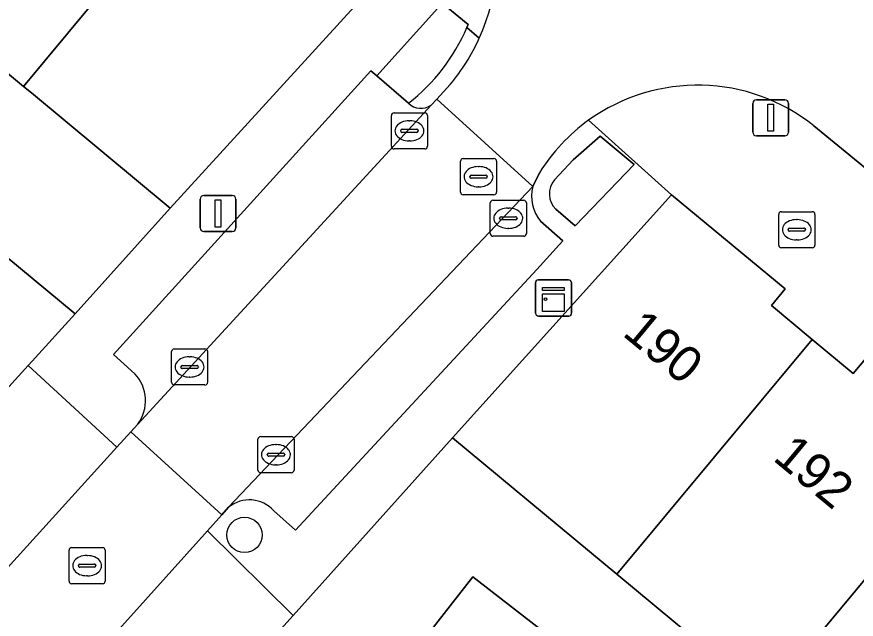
# Model space of a CAD drawing. Extents: x 161881 to 162523, y 381678 to 382381.
# Drawn here: x 162365 to 162388.24, y 381913.58 to 381930.28 of the extents above; entities that cross this region are included whole.
import ezdxf

# ---------------------------------------------------------------- set-up
doc = ezdxf.new("R2010")
doc.units = 0
for name, color, linetype in [('IMGEO_Boom', 7, 'Continuous'), ('IMGEO_Brandkraan', 7, 'Continuous'), ('IMGEO_Erf', 7, 'Continuous'), ('IMGEO_Groenvoorziening', 7, 'Continuous'), ('IMGEO_Kast', 7, 'Continuous'), ('IMGEO_Kolk', 7, 'Continuous'), ('IMGEO_Lichtmast', 7, 'Continuous'), ('IMGEO_Muur', 7, 'Continuous'), ('IMGEO_Pand', 7, 'Continuous'), ('IMGEO_Pand_nummerreeks', 7, 'Continuous'), ('IMGEO_Parkeervlak_open', 7, 'Continuous'), ('IMGEO_Rijbaan_lokaal_open', 7, 'Continuous'), ('IMGEO_Rioolput', 7, 'Continuous'), ('IMGEO_Voetpad_open', 7, 'Continuous')]:
    doc.layers.add(name, color=color, linetype=linetype)

msp = doc.modelspace()

# ---------------------------------------------------------------- linework, layer by layer
at = {"layer": 'IMGEO_Boom'}
msp.add_circle((162371.304, 381915.913), 0.489, dxfattribs=at)
at = {"layer": 'IMGEO_Brandkraan'}
for p, q in [((162386.098, 381923.947), (162386.098, 381924.799)), ((162386.173, 381924.873), (162387.025, 381924.873)), ((162387.099, 381924.799), (162387.099, 381923.947)), ((162386.586, 381924.653), (162386.611, 381924.653)), ((162386.357, 381924.367), (162386.357, 381924.379)), ((162386.795, 381924.33), (162386.397, 381924.33)), ((162386.4, 381924.416), (162386.798, 381924.416)), ((162386.841, 381924.379), (162386.841, 381924.367)), ((162386.609, 381924.093), (162386.584, 381924.093)), ((162387.025, 381923.873), (162386.173, 381923.873))]:
    msp.add_line(p, q, dxfattribs=at)
for points in [[(162386.098, 381923.947), (162386.098, 381924.799)], [(162386.173, 381924.873), (162387.025, 381924.873)], [(162387.099, 381924.799), (162387.099, 381923.947)], [(162387.025, 381923.873), (162386.173, 381923.873)]]:
    msp.add_lwpolyline(points, dxfattribs=at)
for centre, radius, start, end in [((162386.175, 381924.797), 0.0765, 91.552, 178.448), ((162386.175, 381924.797), 0.0765, 91.552, 178.448), ((162387.023, 381924.797), 0.0765, 1.552, 88.448), ((162387.023, 381924.797), 0.0765, 1.552, 88.448), ((162386.397, 381924.376), 0.0403, 85.8775, 175.7526), ((162386.394, 381924.366), 0.0366, 178.938, 274.7102), ((162386.798, 381924.373), 0.043, 264.8664, 352.4533), ((162386.802, 381924.378), 0.0386, 1.7309, 96.639), ((162386.175, 381923.949), 0.0765, 181.552, 268.448), ((162386.175, 381923.949), 0.0765, 181.552, 268.448), ((162387.023, 381923.949), 0.0765, 271.552, 358.448), ((162387.023, 381923.949), 0.0765, 271.552, 358.448)]:
    msp.add_arc(centre, radius, start, end, dxfattribs=at)
for centre, major_axis, ratio, start_param, end_param in [((162386.585, 381924.373), (-0.387, 0.002), 0.722429, 4.712389, 7.853982), ((162386.61, 381924.373), (-0.39, 0.002), 0.717154, 1.570796, 4.712389)]:
    msp.add_ellipse(centre, major_axis=major_axis, ratio=ratio, start_param=start_param, end_param=end_param, dxfattribs=at)
at = {"layer": 'IMGEO_Erf'}
for points in [[(162362.768, 381925.233), (162366.613, 381922.037), (162369.246, 381924.97), (162365.401, 381928.166), (162365.186, 381928.345), (162361.108, 381931.735)], [(162383.306, 381891.633), (162388.53, 381897.921), (162390.835, 381896.006), (162396.322, 381902.611), (162394.016, 381904.526), (162392.495, 381902.696), (162388.778, 381905.783), (162388.37, 381906.122), (162389.891, 381907.952), (162385.752, 381911.39), (162381.619, 381914.822), (162380.911, 381915.41), (162377.065, 381918.605), (162372.654, 381913.683), (162372.054, 381913.013), (162369.869, 381910.575), (162373.57, 381907.213), (162375.958, 381905.043), (162371.892, 381900.569), (162371.822, 381900.491), (162373.921, 381898.584), (162369.929, 381894.191), (162365.442, 381898.267), (162361.741, 381901.629)]]:
    msp.add_lwpolyline(points, dxfattribs=at)
msp.add_lwpolyline([(162376.064, 381908.136), (162374.161, 381909.62), (162373.826, 381909.882), (162377.626, 381914.754), (162380.015, 381912.891), (162377.671, 381910.07), (162381.786, 381906.65), (162380.179, 381904.716)], close=True, dxfattribs=at)
at = {"layer": 'IMGEO_Groenvoorziening'}
for points in [[(162377.462, 381929.977), (162377.495, 381930.057), (162376.782, 381930.65), (162376.741, 381930.606), (162374.965, 381928.638), (162375.845, 381927.879)], [(162379.923, 381924.94), (162380.462, 381924.484), (162382.096, 381926.178), (162381.155, 381926.963), (162380.405, 381926.31), (162379.887, 381925.758)]]:
    msp.add_lwpolyline(points, dxfattribs=at)
for centre, radius, start, end in [((162372.55, 381932.091), 5.347, 308.0367, 336.718), ((162380.361, 381925.369), 0.613, 140.6598, 224.3801)]:
    msp.add_arc(centre, radius, start, end, dxfattribs=at)
at = {"layer": 'IMGEO_Kast'}
for p, q in [((162379.36, 381922.056), (162379.36, 381922.897)), ((162379.36, 381922.897), (162379.36, 381922.056)), ((162379.435, 381922.981), (162380.276, 381922.981)), ((162380.276, 381922.981), (162379.435, 381922.981)), ((162380.36, 381922.906), (162380.36, 381922.065)), ((162380.36, 381922.065), (162380.36, 381922.906)), ((162380.285, 381921.981), (162379.444, 381921.981)), ((162379.444, 381921.981), (162380.285, 381921.981))]:
    msp.add_line(p, q, dxfattribs=at)
for points in [[(162379.555, 381922.771), (162380.155, 381922.771), (162380.155, 381922.686), (162379.555, 381922.686), (162379.555, 381922.771)], [(162379.555, 381922.596), (162380.155, 381922.596), (162380.155, 381922.107), (162379.555, 381922.107), (162379.555, 381922.596)]]:
    msp.add_lwpolyline(points, dxfattribs=at)
msp.add_circle((162379.639, 381922.445), 0.0377, dxfattribs=at)
for centre, start, end in [((162379.438, 381922.903), 92.4484, 184.2845), ((162379.438, 381922.903), 92.4484, 184.2845), ((162380.282, 381922.903), 2.4484, 94.2845), ((162380.282, 381922.903), 2.4484, 94.2845), ((162379.438, 381922.059), 182.4484, 274.2845), ((162379.438, 381922.059), 182.4484, 274.2845), ((162380.282, 381922.059), 272.4484, 4.2845), ((162380.282, 381922.059), 272.4484, 4.2845)]:
    msp.add_arc(centre, 0.0779, start, end, dxfattribs=at)
at = {"layer": 'IMGEO_Kolk'}
for p, q in [((162375.37, 381926.687), (162375.37, 381927.539)), ((162375.445, 381927.613), (162376.297, 381927.613)), ((162376.371, 381927.539), (162376.371, 381926.687)), ((162375.858, 381927.393), (162375.883, 381927.393)), ((162375.629, 381927.107), (162375.629, 381927.119)), ((162376.067, 381927.07), (162375.669, 381927.07)), ((162375.672, 381927.156), (162376.07, 381927.156)), ((162376.113, 381927.119), (162376.113, 381927.107)), ((162375.881, 381926.833), (162375.856, 381926.833)), ((162376.297, 381926.613), (162375.445, 381926.613)), ((162378.183, 381925.191), (162379.035, 381925.191)), ((162378.108, 381924.265), (162378.108, 381925.117)), ((162378.596, 381924.971), (162378.621, 381924.971)), ((162379.109, 381925.117), (162379.109, 381924.265)), ((162378.367, 381924.685), (162378.367, 381924.697)), ((162378.41, 381924.734), (162378.808, 381924.734)), ((162378.851, 381924.697), (162378.851, 381924.685)), ((162378.805, 381924.648), (162378.407, 381924.648)), ((162378.619, 381924.411), (162378.594, 381924.411)), ((162379.035, 381924.191), (162378.183, 381924.191)), ((162369.282, 381920.143), (162369.282, 381920.995)), ((162369.357, 381921.069), (162370.209, 381921.069)), ((162370.283, 381920.995), (162370.283, 381920.143)), ((162369.77, 381920.849), (162369.795, 381920.849)), ((162369.541, 381920.563), (162369.541, 381920.575)), ((162369.979, 381920.526), (162369.581, 381920.526)), ((162369.584, 381920.612), (162369.982, 381920.612)), ((162370.025, 381920.575), (162370.025, 381920.563)), ((162369.793, 381920.289), (162369.768, 381920.289)), ((162370.209, 381920.069), (162369.357, 381920.069)), ((162371.674, 381917.711), (162371.674, 381918.563)), ((162371.749, 381918.637), (162372.601, 381918.637)), ((162372.162, 381918.417), (162372.187, 381918.417)), ((162372.675, 381918.563), (162372.675, 381917.711)), ((162371.976, 381918.18), (162372.374, 381918.18)), ((162371.933, 381918.131), (162371.933, 381918.143)), ((162372.371, 381918.094), (162371.973, 381918.094)), ((162372.417, 381918.143), (162372.417, 381918.131)), ((162372.185, 381917.857), (162372.16, 381917.857)), ((162372.601, 381917.637), (162371.749, 381917.637)), ((162366.445, 381914.635), (162366.445, 381915.487)), ((162366.52, 381915.561), (162367.372, 381915.561)), ((162367.446, 381915.487), (162367.446, 381914.635)), ((162366.933, 381915.341), (162366.958, 381915.341)), ((162366.704, 381915.055), (162366.704, 381915.067)), ((162367.142, 381915.018), (162366.744, 381915.018)), ((162366.747, 381915.104), (162367.145, 381915.104)), ((162367.188, 381915.067), (162367.188, 381915.055)), ((162366.956, 381914.781), (162366.931, 381914.781)), ((162367.372, 381914.561), (162366.52, 381914.561))]:
    msp.add_line(p, q, dxfattribs=at)
for points in [[(162375.37, 381926.687), (162375.37, 381927.539)], [(162375.445, 381927.613), (162376.297, 381927.613)], [(162376.371, 381927.539), (162376.371, 381926.687)], [(162376.297, 381926.613), (162375.445, 381926.613)], [(162378.183, 381925.191), (162379.035, 381925.191)], [(162378.108, 381924.265), (162378.108, 381925.117)], [(162379.109, 381925.117), (162379.109, 381924.265)], [(162379.035, 381924.191), (162378.183, 381924.191)], [(162369.282, 381920.143), (162369.282, 381920.995)], [(162369.357, 381921.069), (162370.209, 381921.069)], [(162370.283, 381920.995), (162370.283, 381920.143)], [(162370.209, 381920.069), (162369.357, 381920.069)], [(162371.674, 381917.711), (162371.674, 381918.563)], [(162371.749, 381918.637), (162372.601, 381918.637)], [(162372.675, 381918.563), (162372.675, 381917.711)], [(162372.601, 381917.637), (162371.749, 381917.637)], [(162366.445, 381914.635), (162366.445, 381915.487)], [(162366.52, 381915.561), (162367.372, 381915.561)], [(162367.446, 381915.487), (162367.446, 381914.635)], [(162367.372, 381914.561), (162366.52, 381914.561)]]:
    msp.add_lwpolyline(points, dxfattribs=at)
for centre, radius, start, end in [((162375.447, 381927.537), 0.0765, 91.552, 178.448), ((162375.447, 381927.537), 0.0765, 91.552, 178.448), ((162376.295, 381927.537), 0.0765, 1.552, 88.448), ((162376.295, 381927.537), 0.0765, 1.552, 88.448), ((162375.669, 381927.116), 0.0403, 85.8775, 175.7526), ((162375.666, 381927.106), 0.0366, 178.938, 274.7102), ((162376.07, 381927.113), 0.043, 264.8664, 352.4533), ((162376.074, 381927.118), 0.0386, 1.7309, 96.639), ((162375.447, 381926.689), 0.0765, 181.552, 268.448), ((162375.447, 381926.689), 0.0765, 181.552, 268.448), ((162376.295, 381926.689), 0.0765, 271.552, 358.448), ((162376.295, 381926.689), 0.0765, 271.552, 358.448), ((162378.185, 381925.115), 0.0765, 91.552, 178.448), ((162378.185, 381925.115), 0.0765, 91.552, 178.448), ((162379.033, 381925.115), 0.0765, 1.552, 88.448), ((162379.033, 381925.115), 0.0765, 1.552, 88.448), ((162378.407, 381924.694), 0.0403, 85.8775, 175.7526), ((162378.404, 381924.684), 0.0366, 178.938, 274.7102), ((162378.808, 381924.691), 0.043, 264.8664, 352.4533), ((162378.812, 381924.696), 0.0386, 1.7309, 96.639), ((162378.185, 381924.267), 0.0765, 181.552, 268.448), ((162378.185, 381924.267), 0.0765, 181.552, 268.448), ((162379.033, 381924.267), 0.0765, 271.552, 358.448), ((162379.033, 381924.267), 0.0765, 271.552, 358.448), ((162369.359, 381920.993), 0.0765, 91.552, 178.448), ((162369.359, 381920.993), 0.0765, 91.552, 178.448), ((162370.207, 381920.993), 0.0765, 1.552, 88.448), ((162370.207, 381920.993), 0.0765, 1.552, 88.448), ((162369.581, 381920.572), 0.0403, 85.8775, 175.7526), ((162369.578, 381920.562), 0.0366, 178.938, 274.7102), ((162369.982, 381920.569), 0.043, 264.8664, 352.4533), ((162369.986, 381920.574), 0.0386, 1.7309, 96.639), ((162369.359, 381920.145), 0.0765, 181.552, 268.448), ((162369.359, 381920.145), 0.0765, 181.552, 268.448), ((162370.207, 381920.145), 0.0765, 271.552, 358.448), ((162370.207, 381920.145), 0.0765, 271.552, 358.448), ((162371.751, 381918.561), 0.0765, 91.552, 178.448), ((162371.751, 381918.561), 0.0765, 91.552, 178.448), ((162372.599, 381918.561), 0.0765, 1.552, 88.448), ((162372.599, 381918.561), 0.0765, 1.552, 88.448), ((162371.973, 381918.14), 0.0403, 85.8775, 175.7526), ((162372.378, 381918.142), 0.0386, 1.7309, 96.639), ((162371.97, 381918.13), 0.0366, 178.938, 274.7102), ((162372.374, 381918.137), 0.043, 264.8664, 352.4533), ((162371.751, 381917.713), 0.0765, 181.552, 268.448), ((162371.751, 381917.713), 0.0765, 181.552, 268.448), ((162372.599, 381917.713), 0.0765, 271.552, 358.448), ((162372.599, 381917.713), 0.0765, 271.552, 358.448), ((162366.522, 381915.485), 0.0765, 91.552, 178.448), ((162366.522, 381915.485), 0.0765, 91.552, 178.448), ((162367.37, 381915.485), 0.0765, 1.552, 88.448), ((162367.37, 381915.485), 0.0765, 1.552, 88.448), ((162366.744, 381915.064), 0.0403, 85.8775, 175.7526), ((162366.741, 381915.054), 0.0366, 178.938, 274.7102), ((162367.145, 381915.061), 0.043, 264.8664, 352.4533), ((162367.149, 381915.066), 0.0386, 1.7309, 96.639), ((162366.522, 381914.637), 0.0765, 181.552, 268.448), ((162366.522, 381914.637), 0.0765, 181.552, 268.448), ((162367.37, 381914.637), 0.0765, 271.552, 358.448), ((162367.37, 381914.637), 0.0765, 271.552, 358.448)]:
    msp.add_arc(centre, radius, start, end, dxfattribs=at)
for centre, major_axis, ratio, start_param, end_param in [((162375.857, 381927.113), (-0.387, 0.002), 0.722429, 4.712389, 7.853982), ((162375.882, 381927.113), (-0.39, 0.002), 0.717154, 1.570796, 4.712389), ((162378.595, 381924.691), (-0.387, 0.002), 0.722429, 4.712389, 7.853982), ((162378.62, 381924.691), (-0.39, 0.002), 0.717154, 1.570796, 4.712389), ((162369.769, 381920.569), (-0.387, 0.002), 0.722429, 4.712389, 7.853982), ((162369.794, 381920.569), (-0.39, 0.002), 0.717154, 1.570796, 4.712389), ((162372.161, 381918.137), (-0.387, 0.002), 0.722429, 4.712389, 7.853982), ((162372.186, 381918.137), (-0.39, 0.002), 0.717154, 1.570796, 4.712389), ((162366.932, 381915.061), (-0.387, 0.002), 0.722429, 4.712389, 7.853982), ((162366.957, 381915.061), (-0.39, 0.002), 0.717154, 1.570796, 4.712389)]:
    msp.add_ellipse(centre, major_axis=major_axis, ratio=ratio, start_param=start_param, end_param=end_param, dxfattribs=at)
at = {"layer": 'IMGEO_Lichtmast'}
for p, q in [((162385.479, 381927.976), (162386.269, 381927.976)), ((162386.269, 381927.976), (162385.479, 381927.976)), ((162385.379, 381927.076), (162385.379, 381927.876)), ((162385.379, 381927.876), (162385.379, 381927.076)), ((162386.369, 381927.876), (162386.369, 381927.076)), ((162386.369, 381927.076), (162386.369, 381927.876)), ((162386.269, 381926.976), (162385.479, 381926.976)), ((162385.479, 381926.976), (162386.269, 381926.976)), ((162370.075, 381924.422), (162370.075, 381925.222)), ((162370.075, 381925.222), (162370.075, 381924.422)), ((162370.175, 381925.322), (162370.965, 381925.322)), ((162370.965, 381925.322), (162370.175, 381925.322)), ((162371.065, 381925.222), (162371.065, 381924.422)), ((162371.065, 381924.422), (162371.065, 381925.222)), ((162370.965, 381924.322), (162370.175, 381924.322)), ((162370.175, 381924.322), (162370.965, 381924.322))]:
    msp.add_line(p, q, dxfattribs=at)
for points in [[(162385.799, 381927.851), (162385.949, 381927.851), (162385.949, 381927.101), (162385.799, 381927.101), (162385.799, 381927.851)], [(162370.495, 381925.197), (162370.645, 381925.197), (162370.645, 381924.447), (162370.495, 381924.447), (162370.495, 381925.197)]]:
    msp.add_lwpolyline(points, dxfattribs=at)
for centre, start, end in [((162385.479, 381927.876), 90, 180), ((162385.479, 381927.876), 90, 180), ((162386.269, 381927.876), 0, 90), ((162386.269, 381927.876), 360, 90), ((162385.479, 381927.076), 180, 270), ((162385.479, 381927.076), 180, 270), ((162386.269, 381927.076), 270, 0), ((162386.269, 381927.076), 270, 0), ((162370.175, 381925.222), 90, 180), ((162370.175, 381925.222), 90, 180), ((162370.965, 381925.222), 0, 90), ((162370.965, 381925.222), 360, 90), ((162370.175, 381924.422), 180, 270), ((162370.175, 381924.422), 180, 270), ((162370.965, 381924.422), 270, 0), ((162370.965, 381924.422), 270, 0)]:
    msp.add_arc(centre, 0.1, start, end, dxfattribs=at)
at = {"layer": 'IMGEO_Muur'}
for points in [[(162369.246, 381924.97), (162366.613, 381922.037)], [(162377.065, 381918.605), (162372.654, 381913.683)], [(162372.654, 381913.683), (162372.054, 381913.013)]]:
    msp.add_lwpolyline(points, dxfattribs=at)
at = {"layer": 'IMGEO_Pand'}
for points in [[(162370.688, 381934.975), (162369.409, 381936.038), (162369.763, 381936.465), (162366.966, 381938.791), (162361.108, 381931.735), (162365.186, 381928.345)], [(162375.427, 381931.75), (162371.039, 381935.397), (162370.688, 381934.975), (162365.186, 381928.345), (162365.401, 381928.166), (162369.246, 381924.97)], [(162362.768, 381925.233), (162362.67, 381925.315), (162361.323, 381923.692), (162359.313, 381921.271), (162363.07, 381918.146), (162365.317, 381920.614), (162365.423, 381920.73), (162366.613, 381922.037)], [(162381.619, 381914.822), (162387.028, 381921.332), (162385.894, 381922.274), (162386.275, 381922.731), (162383.131, 381925.342), (162377.065, 381918.605), (162380.911, 381915.41)], [(162385.752, 381911.39), (162391.545, 381918.362), (162388.545, 381920.853), (162388.161, 381920.391), (162387.028, 381921.332), (162381.619, 381914.822)], [(162385.752, 381911.39), (162389.891, 381907.952), (162395.307, 381914.468), (162394.169, 381915.414), (162394.547, 381915.869), (162391.545, 381918.362)], [(162380.015, 381912.891), (162377.626, 381914.754), (162373.826, 381909.882), (162374.161, 381909.62), (162376.064, 381908.136), (162377.671, 381910.07)]]:
    msp.add_lwpolyline(points, close=True, dxfattribs=at)
at = {"layer": 'IMGEO_Parkeervlak_open'}
for points in [[(162375.845, 381927.879), (162374.965, 381928.638), (162374.804, 381928.776), (162367.672, 381920.918), (162368.264, 381920.381)], [(162368.347, 381918.986), (162376.471, 381927.827)], [(162379.286, 381925.567), (162370.863, 381916.679)], [(162372.118, 381916.58), (162372.714, 381916.046), (162379.399, 381923.266), (162380.121, 381924.063), (162379.503, 381924.613)]]:
    msp.add_lwpolyline(points, dxfattribs=at)
for centre, radius, start, end in [((162376.19, 381928.239), 0.499, 226.2051, 304.2979), ((162380.331, 381925.303), 1.078, 165.8208, 219.8085), ((162367.485, 381919.635), 1.078, 323.0217, 43.7882), ((162371.439, 381915.976), 0.909, 41.656, 129.3232)]:
    msp.add_arc(centre, radius, start, end, dxfattribs=at)
at = {"layer": 'IMGEO_Rijbaan_lokaal_open'}
for points in [[(162377.001, 381928.403), (162376.626, 381927.996), (162379.286, 381925.567), (162379.472, 381925.953)], [(162387.072, 381927.252), (162390.287, 381924.609), (162391.437, 381925.971), (162392.314, 381927.01), (162392.987, 381927.807), (162393.04, 381927.87)]]:
    msp.add_lwpolyline(points, dxfattribs=at)
for points in [[(162368.347, 381918.986), (162368.155, 381918.773), (162370.672, 381916.467), (162370.863, 381916.679), (162379.286, 381925.567), (162376.626, 381927.996), (162376.471, 381927.827)], [(162370.672, 381916.467), (162368.155, 381918.773), (162367.769, 381918.348), (162363.656, 381913.817), (162363.341, 381913.47), (162365.896, 381911.151), (162366.189, 381911.476), (162370.278, 381916.028)]]:
    msp.add_lwpolyline(points, close=True, dxfattribs=at)
for centre, radius, start, end in [((162372.822, 381931.927), 5.466, 335.7145, 57.383), ((162372.851, 381931.905), 5.43, 319.838, 335.7968), ((162383.85, 381923.218), 5.162, 51.3827, 125.7902), ((162383.871, 381923.2), 5.19, 125.8635, 147.9657)]:
    msp.add_arc(centre, radius, start, end, dxfattribs=at)
at = {"layer": 'IMGEO_Rioolput'}
for p, q in [((162377.36, 381926.343), (162378.212, 381926.343)), ((162377.285, 381925.417), (162377.285, 381926.269)), ((162377.773, 381926.123), (162377.798, 381926.123)), ((162378.286, 381926.269), (162378.286, 381925.417)), ((162377.544, 381925.837), (162377.544, 381925.849)), ((162377.587, 381925.886), (162377.985, 381925.886)), ((162378.028, 381925.849), (162378.028, 381925.837)), ((162377.982, 381925.8), (162377.584, 381925.8)), ((162377.796, 381925.563), (162377.771, 381925.563)), ((162378.212, 381925.343), (162377.36, 381925.343))]:
    msp.add_line(p, q, dxfattribs=at)
for points in [[(162377.36, 381926.343), (162378.212, 381926.343)], [(162377.285, 381925.417), (162377.285, 381926.269)], [(162378.286, 381926.269), (162378.286, 381925.417)], [(162378.212, 381925.343), (162377.36, 381925.343)]]:
    msp.add_lwpolyline(points, dxfattribs=at)
for centre, radius, start, end in [((162377.362, 381926.267), 0.0765, 91.552, 178.448), ((162377.362, 381926.267), 0.0765, 91.552, 178.448), ((162378.21, 381926.267), 0.0765, 1.552, 88.448), ((162378.21, 381926.267), 0.0765, 1.552, 88.448), ((162377.584, 381925.846), 0.0403, 85.8775, 175.7526), ((162377.989, 381925.848), 0.0386, 1.7309, 96.639), ((162377.581, 381925.836), 0.0366, 178.938, 274.7102), ((162377.985, 381925.843), 0.043, 264.8664, 352.4533), ((162377.362, 381925.419), 0.0765, 181.552, 268.448), ((162377.362, 381925.419), 0.0765, 181.552, 268.448), ((162378.21, 381925.419), 0.0765, 271.552, 358.448), ((162378.21, 381925.419), 0.0765, 271.552, 358.448)]:
    msp.add_arc(centre, radius, start, end, dxfattribs=at)
for centre, major_axis, ratio, start_param, end_param in [((162377.772, 381925.843), (-0.387, 0.002), 0.722429, 4.712389, 7.853982), ((162377.797, 381925.843), (-0.39, 0.002), 0.717154, 1.570796, 4.712389)]:
    msp.add_ellipse(centre, major_axis=major_axis, ratio=ratio, start_param=start_param, end_param=end_param, dxfattribs=at)
at = {"layer": 'IMGEO_Voetpad_open'}
for points in [[(162363.876, 381941.359), (162366.966, 381938.791), (162369.763, 381936.465), (162369.409, 381936.038), (162370.688, 381934.975), (162371.039, 381935.397), (162375.427, 381931.75), (162376.741, 381930.606), (162376.782, 381930.65), (162377.495, 381930.057), (162377.462, 381929.977), (162377.804, 381929.679)], [(162374.804, 381928.776), (162374.965, 381928.638), (162376.741, 381930.606), (162375.427, 381931.75), (162369.246, 381924.97), (162366.613, 381922.037), (162365.423, 381920.73), (162365.317, 381920.614), (162367.769, 381918.348), (162368.155, 381918.773), (162368.347, 381918.986)], [(162377.804, 381929.679), (162377.462, 381929.977)], [(162368.264, 381920.381), (162367.672, 381920.918), (162374.804, 381928.776)], [(162376.471, 381927.827), (162376.626, 381927.996), (162377.001, 381928.403)], [(162383.131, 381925.342), (162380.831, 381927.406)], [(162380.831, 381927.406), (162383.131, 381925.342), (162386.275, 381922.731), (162385.894, 381922.274), (162387.028, 381921.332), (162388.161, 381920.391), (162388.545, 381920.853), (162391.545, 381918.362), (162394.547, 381915.869), (162394.169, 381915.414), (162395.307, 381914.468), (162396.443, 381913.525), (162396.791, 381913.944), (162399.779, 381911.463), (162402.766, 381908.982), (162402.423, 381908.569), (162403.544, 381907.638), (162404.664, 381906.707), (162405.036, 381907.154), (162408.147, 381904.571), (162416.178, 381897.901), (162417.532, 381897.014)], [(162392.553, 381922.745), (162390.287, 381924.609), (162387.072, 381927.252)], [(162379.887, 381925.758), (162380.405, 381926.31), (162381.155, 381926.963), (162382.096, 381926.178), (162380.462, 381924.484), (162379.923, 381924.94)], [(162379.472, 381925.953), (162379.286, 381925.567)], [(162370.863, 381916.679), (162370.672, 381916.467), (162370.278, 381916.028), (162372.654, 381913.683), (162377.065, 381918.605), (162383.131, 381925.342)], [(162379.503, 381924.613), (162380.121, 381924.063), (162379.399, 381923.266), (162372.714, 381916.046), (162372.118, 381916.58)]]:
    msp.add_lwpolyline(points, dxfattribs=at)
for points in [[(162363.656, 381913.817), (162367.769, 381918.348), (162365.317, 381920.614), (162363.07, 381918.146), (162362.239, 381917.205), (162361.239, 381916.098)], [(162372.054, 381913.013), (162372.654, 381913.683), (162370.278, 381916.028), (162366.189, 381911.476), (162367.357, 381910.439), (162368.679, 381909.266), (162369.869, 381910.575)]]:
    msp.add_lwpolyline(points, close=True, dxfattribs=at)
for centre, radius, start, end in [((162372.822, 381931.927), 5.466, 335.7145, 57.383), ((162372.55, 381932.091), 5.347, 308.0367, 336.718), ((162372.851, 381931.905), 5.43, 319.838, 335.7968), ((162383.85, 381923.218), 5.162, 51.3827, 125.7902), ((162376.19, 381928.239), 0.499, 226.2051, 304.2979), ((162383.871, 381923.2), 5.19, 125.8635, 147.9657), ((162380.361, 381925.369), 0.613, 140.6598, 224.3801), ((162380.331, 381925.303), 1.078, 165.8208, 219.8085), ((162367.485, 381919.635), 1.078, 323.0217, 43.7882), ((162371.439, 381915.976), 0.909, 41.656, 129.3232)]:
    msp.add_arc(centre, radius, start, end, dxfattribs=at)

# ---------------------------------------------------------------- texts
at = {"layer": 'IMGEO_Pand_nummerreeks'}
for s, p in [('190', (162381.738, 381921.463)), ('192', (162385.906, 381918.005))]:
    msp.add_text(s, height=1, rotation=320.3174, dxfattribs=at).set_placement(p)

doc.saveas('drawing.dxf')
